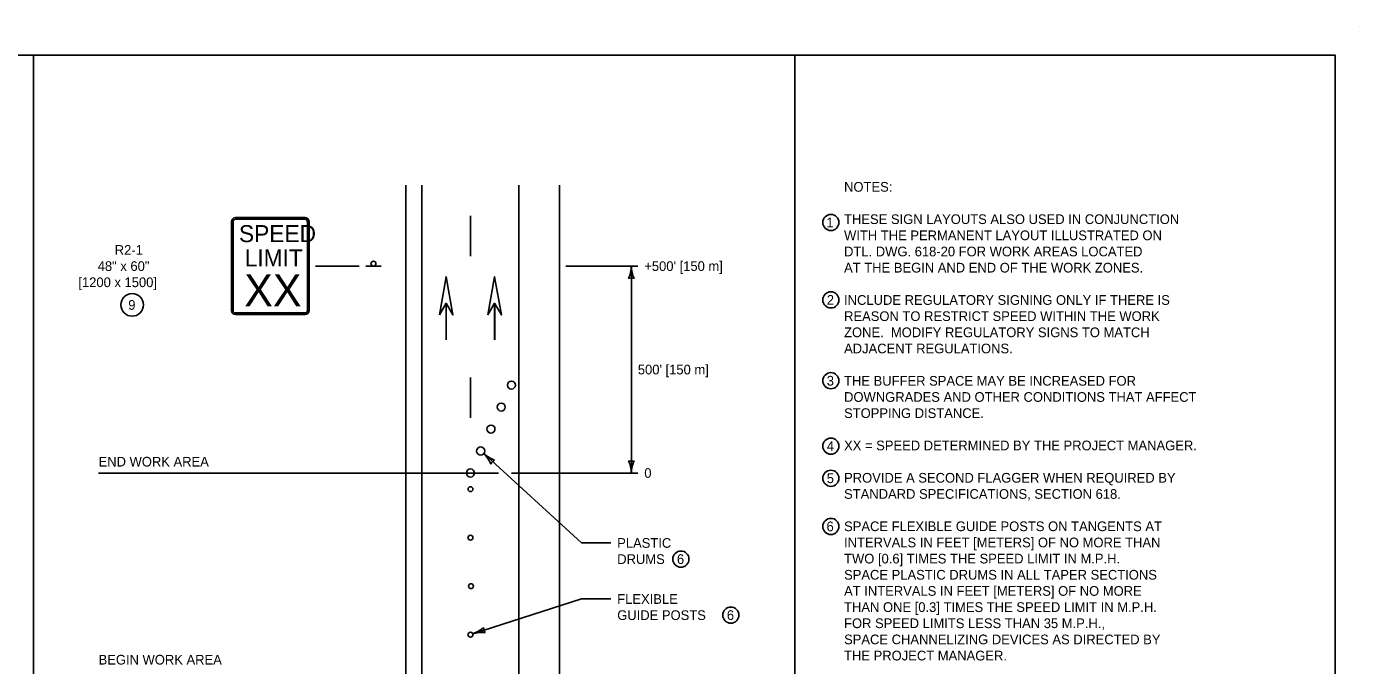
# Model space of a CAD drawing. Extents: x 49991.4 to 50021, y 49987.6 to 50011.4.
# Drawn here: x 50008.66 to 50016.9, y 49995.22 to 49999.18 of the extents above; entities that cross this region are included whole.
import ezdxf

# ---------------------------------------------------------------- set-up
doc = ezdxf.new("R2010")
doc.units = 0
for name, color, linetype in [('Level 1', 7, 'Continuous'), ('Level 2', 7, 'Continuous'), ('Level 3', 7, 'Continuous')]:
    doc.layers.add(name, color=color, linetype=linetype)

msp = doc.modelspace()

# ---------------------------------------------------------------- linework, layer by layer
at = {"layer": 'Level 1'}
for p, q in [((50016.9001, 49999.1756), (50016.9001, 49999.1756)), ((50011.0016, 49989.429), (50011.0016, 49998.194)), ((50011.1016, 49989.429), (50011.1016, 49998.194)), ((50011.7016, 49989.429), (50011.7016, 49998.194)), ((50011.9516, 49989.429), (50011.9516, 49998.194)), ((50011.4016, 49997.7546), (50011.4016, 49998.0046)), ((50009.9236, 49997.419), (50009.9236, 49997.969)), ((50009.9336, 49997.419), (50009.9336, 49997.969)), ((50009.9486, 49997.994), (50010.3786, 49997.994)), ((50009.9486, 49997.984), (50010.3786, 49997.984)), ((50010.3936, 49997.969), (50010.3936, 49997.419)), ((50010.4036, 49997.969), (50010.4036, 49997.419)), ((50010.7536, 49997.694), (50010.8496, 49997.694)), ((50011.2513, 49997.2385), (50011.2513, 49997.4644)), ((50011.2516, 49997.2385), (50011.2516, 49997.4644)), ((50011.5513, 49997.2385), (50011.5513, 49997.4644)), ((50011.5516, 49997.2385), (50011.5516, 49997.4644)), ((50010.3786, 49997.404), (50009.9486, 49997.404)), ((50010.3786, 49997.394), (50009.9486, 49997.394)), ((50011.4016, 49996.7546), (50011.4016, 49997.0046))]:
    msp.add_line(p, q, dxfattribs=at)
for points in [[(49999.3835, 49998.9992), (50016.7501, 49998.9992), (50016.7501, 49987.7988), (49999.3835, 49987.7988)], [(50011.2096, 49997.3921), (50011.2513, 49997.6286), (50011.2932, 49997.3921), (50011.2513, 49997.4643)], [(50011.5096, 49997.3921), (50011.5513, 49997.6286), (50011.5932, 49997.3921), (50011.5513, 49997.4643)]]:
    msp.add_lwpolyline(points, close=True, dxfattribs=at)
for centre, radius in [((50010.8016, 49997.7092), 0.0152), ((50011.6552, 49996.9578), 0.025), ((50011.5918, 49996.8219), 0.025), ((50011.5284, 49996.6859), 0.025), ((50011.465, 49996.55), 0.025), ((50011.4016, 49996.414), 0.025), ((50011.4016, 49996.314), 0.015), ((50011.4016, 49996.014), 0.015), ((50011.4053, 49995.714), 0.015), ((50011.4016, 49995.414), 0.015)]:
    msp.add_circle(centre, radius, dxfattribs=at)
for centre, radius, start, end in [((50009.9486, 49997.969), 0.025, 90, 180), ((50009.9486, 49997.969), 0.015, 90, 180), ((50010.3786, 49997.969), 0.025, 0, 90), ((50010.3786, 49997.969), 0.015, 0, 90), ((50009.9486, 49997.419), 0.025, 180, 270), ((50009.9486, 49997.419), 0.015, 180, 270), ((50010.3786, 49997.419), 0.025, 270, 0), ((50010.3786, 49997.419), 0.015, 270, 0)]:
    msp.add_arc(centre, radius, start, end, dxfattribs=at)
at = {"layer": 'Level 2'}
for centre, radius in [((50013.631, 49997.964), 0.05), ((50009.3094, 49997.454), 0.07), ((50013.631, 49997.485), 0.05), ((50013.631, 49996.9849), 0.05), ((50013.631, 49996.5804), 0.05), ((50013.631, 49996.3814), 0.05), ((50013.631, 49996.0835), 0.05), ((50012.7035, 49995.8813), 0.05), ((50013.0123, 49995.5349), 0.05)]:
    msp.add_circle(centre, radius, dxfattribs=at)
at = {"layer": 'Level 3'}
for p, q in [((50008.6982, 49998.9992), (50008.6982, 49987.7988)), ((50013.4076, 49998.9992), (50013.4076, 49987.7988)), ((50010.7136, 49997.694), (50010.4436, 49997.694)), ((50012.437, 49997.694), (50011.9916, 49997.694)), ((50012.397, 49997.054), (50012.397, 49997.694)), ((50012.397, 49996.414), (50012.397, 49997.054)), ((50011.4844, 49996.5341), (50012.0895, 49995.9812)), ((50011.5758, 49996.414), (50009.1014, 49996.414)), ((50011.6824, 49996.414), (50011.6558, 49996.414)), ((50012.437, 49996.414), (50011.6824, 49996.414)), ((50012.0895, 49995.9812), (50012.2695, 49995.9812)), ((50011.4157, 49995.4193), (50012.0895, 49995.6346)), ((50012.0895, 49995.6346), (50012.2695, 49995.6346))]:
    msp.add_line(p, q, dxfattribs=at)
for centre, radius, start, end in [((50012.1643, 49997.7055), 0.233, 337.92284, 357.17269), ((50012.6191, 49997.7032), 0.2223, 182.36048, 202.54399), ((50012.397, 49997.5658), 0.0548, 72.13882, 107.86118), ((50011.6306, 49996.7016), 0.2223, 228.88386, 249.06736), ((50011.3159, 49996.3732), 0.233, 24.44621, 43.69606), ((50011.5774, 49996.4459), 0.0548, 118.66219, 154.38456), ((50012.1749, 49996.4048), 0.2223, 2.36048, 22.54399), ((50012.397, 49996.5422), 0.0548, 252.13882, 287.86118), ((50012.6297, 49996.4025), 0.233, 157.92284, 177.17269), ((50011.3339, 49995.6375), 0.233, 290.54921, 309.79906), ((50011.5378, 49995.4583), 0.0548, 179.86072, 215.58308), ((50011.4746, 49995.2049), 0.2223, 85.17791, 105.36142)]:
    msp.add_arc(centre, radius, start, end, dxfattribs=at)

# ---------------------------------------------------------------- texts
at = {"layer": 'Level 1'}
for s, height, p in [('SPEED', 0.10512, (50009.9698, 49997.8424)), ('LIMIT', 0.10512, (50010.0052, 49997.6923)), ('XX', 0.19892, (50010.002, 49997.445))]:
    msp.add_text(s, height=height, dxfattribs=at).set_placement(p)
at = {"layer": 'Level 2'}
for s, p in [('NOTES:', (50013.7128, 49998.1544)), ('THESE SIGN LAYOUTS ALSO USED IN CONJUNCTION', (50013.7128, 49997.9544)), ('1', (50013.6034, 49997.934)), ('WITH THE PERMANENT LAYOUT ILLUSTRATED ON', (50013.7128, 49997.8544)), ('R2-1', (50009.2014, 49997.764)), ('DTL. DWG. 618-20 FOR WORK AREAS LOCATED', (50013.7128, 49997.7544)), ('48" x 60"', (50009.0959, 49997.664)), ("+500' [150 m]", (50012.477, 49997.664)), ('AT THE BEGIN AND END OF THE WORK ZONES.', (50013.7128, 49997.6544)), ('[1200 x 1500]', (50008.9764, 49997.564)), ('2', (50013.6058, 49997.455)), ('INCLUDE REGULATORY SIGNING ONLY IF THERE IS', (50013.7128, 49997.4544)), ('9', (50009.2849, 49997.424)), ('REASON TO RESTRICT SPEED WITHIN THE WORK', (50013.7128, 49997.3544)), ('ZONE.  MODIFY REGULATORY SIGNS TO MATCH', (50013.7128, 49997.2544)), ('ADJACENT REGULATIONS.', (50013.7128, 49997.1544)), ("500' [150 m]", (50012.437, 49997.024)), ('3', (50013.6058, 49996.9549)), ('THE BUFFER SPACE MAY BE INCREASED FOR', (50013.7128, 49996.9544)), ('DOWNGRADES AND OTHER CONDITIONS THAT AFFECT', (50013.7128, 49996.8544)), ('STOPPING DISTANCE.', (50013.7128, 49996.7544)), ('4', (50013.6058, 49996.5504)), ('XX = SPEED DETERMINED BY THE PROJECT MANAGER.', (50013.7128, 49996.5544)), ('END WORK AREA', (50009.1014, 49996.454)), ('0', (50012.477, 49996.384)), ('5', (50013.6058, 49996.3514)), ('PROVIDE A SECOND FLAGGER WHEN REQUIRED BY', (50013.7128, 49996.3544)), ('STANDARD SPECIFICATIONS, SECTION 618.', (50013.7128, 49996.2544)), ('6', (50013.6042, 49996.0535)), ('SPACE FLEXIBLE GUIDE POSTS ON TANGENTS AT', (50013.7128, 49996.0544)), ('PLASTIC', (50012.3095, 49995.9513)), ('INTERVALS IN FEET [METERS] OF NO MORE THAN ', (50013.7128, 49995.9544)), ('DRUMS', (50012.3095, 49995.8513)), ('6', (50012.679, 49995.8513)), ('TWO [0.6] TIMES THE SPEED LIMIT IN M.P.H.', (50013.7128, 49995.8544)), ('SPACE PLASTIC DRUMS IN ALL TAPER SECTIONS', (50013.7128, 49995.7544)), ('AT INTERVALS IN FEET [METERS] OF NO MORE', (50013.7128, 49995.6544)), ('FLEXIBLE', (50012.3095, 49995.6046)), ('THAN ONE [0.3] TIMES THE SPEED LIMIT IN M.P.H.', (50013.7128, 49995.5544)), ('GUIDE POSTS', (50012.3095, 49995.5046)), ('6', (50012.9877, 49995.5049)), ('FOR SPEED LIMITS LESS THAN 35 M.P.H.,', (50013.7128, 49995.4544)), ('SPACE CHANNELIZING DEVICES AS DIRECTED BY', (50013.7128, 49995.3544)), ('BEGIN WORK AREA', (50009.1014, 49995.229)), ('THE PROJECT MANAGER.', (50013.7128, 49995.2544))]:
    msp.add_text(s, height=0.06, dxfattribs=at).set_placement(p)

doc.saveas('drawing.dxf')
